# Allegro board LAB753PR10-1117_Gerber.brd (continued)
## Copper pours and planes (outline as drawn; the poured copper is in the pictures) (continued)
VCORE_VDDP on BOTTOM (solid shape): 135.66,125.98 135.66,125.9 135.02,125.26 133.36,125.26 132.53,124.43 132.53,124.17 132.91,123.79 132.91,123.6 132.65,123.34 132.4,123.34 132.02,123.73 132.02,124.11 131.64,124.49 131.64,124.88 132.77,126.02 132.96,126.02 133.24,125.75 134.39,125.75 134.65,125.48 134.95,125.48 135.51,126.04 135.59,126.04
VID_PLLVDD on TOP (solid shape): 153.84,99.44 153.84,98.99 154.94,97.88 154.94,96.87 154.78,96.72 154.02,96.72 153.8,96.49 153.8,95.54 153.61,95.36 152.6,95.36 152.42,95.54 152.42,99.4 152.54,99.53 153.74,99.53
VL on TOP (solid shape): 27.18,31.08 27.18,28.98 27.12,28.92 24.46,28.92 24.42,28.96 24.42,29.11 24.45,29.14 25.41,29.14 25.48,29.21 25.82,29.21 25.83,29.21 26.08,29.21 26.22,29.35 26.22,29.44 26.22,29.45 26.27,29.62 26.22,29.79 26.22,29.8 26.22,31.04 26.3,31.13 27.13,31.13
N3691782 on BOTTOM (solid shape): 257.97,29.04 257.97,27.05 257.81,26.88 256.15,26.88 256.07,26.96 256.07,27.97 256.74,28.64 256.74,29.2 256.78,29.23 257.78,29.23
N4123550 on TOP (solid shape): 36.64,20.92 36.64,20.28 35.56,19.2 35.56,18.76 35.37,18.57 33.78,18.57 33.72,18.63 33.72,19.65 33.78,19.71 34.42,19.71 35.69,20.98 36.58,20.98
N4124695 on TOP (solid shape): 24.83,33.86 24.83,33.23 23.1,33.23 23,33.33 23,33.81 23.08,33.89 24.81,33.89
N16788038 on TOP (solid shape): 44.83,21.05 44.83,20.22 44.58,19.97 42.93,19.97 42.8,20.09 42.8,21.11 42.93,21.24 44.64,21.24
N16788038 on BOTTOM (solid shape): 39.11,18.3 39.11,17.77 39.08,17.74 38.46,17.74 38.2,17.49 38.2,16.05 38.16,16.01 37.6,16.01 37.33,16.28 37.33,17.3 36.9,17.74 36.9,18.12 37.12,18.34 39.07,18.34
N18410136 on BOTTOM (solid shape): 137.29,107.28 137.29,106.52 137.19,106.42 135.06,106.42 134.99,106.49 134.99,107.34 135.06,107.41 137.16,107.41
N20620737 on TOP (solid shape): 182.86,30.16 182.86,29.58 182.8,29.52 181.43,29.52 181.22,29.31 181.22,28.74 181.22,28.74 181.22,28.53 181.13,28.44 181.13,27.57 181.06,27.5 180.93,27.5 180.87,27.57 180.87,28.76 180.95,28.84 180.95,29.02 180.95,29.03 180.96,29.14 180.95,29.24 180.95,29.25 180.95,29.38 180.8,29.53 180.71,29.53 180.65,29.59 180.65,30.19 180.71,30.25 182.77,30.25
N26316553 on TOP (solid shape): 104.02,119.98 104.02,117.69 103.89,117.57 103.38,117.57 103.25,117.69 103.25,118.65 102.81,119.09 102.49,119.09 102.3,119.28 102.3,119.66 102.43,119.79 102.94,119.79 103.25,120.11 103.89,120.11
N27543768 on BOTTOM (solid shape): 268,37.42 268,35.41 266.74,34.15 266.74,33.33 265.88,32.46 265.88,31.74 265.63,31.5 265.44,31.5 264.33,32.61 264.33,33.84 264.84,34.34 264.84,36.51 266.51,38.19 267.22,38.19
N27863843 on TOP (solid shape): 158.75,21.05 158.75,20.47 159.2,20.03 159.83,20.03 160.68,19.18 160.68,18.1 160.61,18.02 160.48,18.02 160.4,18.1 160.4,18.7 159.64,19.46 158.88,19.46 158.15,20.19 158.15,21.08 158.18,21.11 158.69,21.11
N30468201 on BOTTOM (solid shape): 32.16,16.83 32.63,16.83 32.77,16.69 32.77,15.65 32.58,15.46 32.2,15.46 31.18,16.47 31.18,17.22 31.35,17.38 31.61,17.38
N30468201 on BOTTOM (solid shape): 39.82,18.33 39.82,17.3 39.42,16.91 38.57,16.91 38.52,16.95 38.52,17.47 38.57,17.52 39.07,17.52 39.23,17.68 39.23,18.29 39.36,18.41 39.74,18.41
N30468201 on IN4 (solid shape): 39.82,18.32 39.82,17.36 38.25,15.8 32.18,15.8 31.18,16.8 31.18,17.02 36.27,17.02 36.27,16.97 36.28,16.92 36.3,16.86 36.32,16.82 36.35,16.77 36.39,16.73 36.43,16.7 36.47,16.67 36.52,16.65 36.58,16.64 36.63,16.64 36.68,16.64 36.73,16.65 36.78,16.67 36.83,16.7 36.87,16.73 36.91,16.77 36.94,16.82 36.96,16.86 36.98,16.92 36.98,16.97 36.98,17.02 36.98,17.07 36.96,17.13 36.94,17.17 36.91,17.22 36.87,17.26 36.83,17.29 36.78,17.32 36.73,17.34 36.68,17.35 36.63,17.35 36.58,17.35 36.52,17.34 36.47,17.32 36.43,17.29 36.39,17.26 36.35,17.22 36.32,17.17 36.3,17.13 36.28,17.07 36.27,17.02 31.18,17.02 31.18,17.33 31.51,17.66 36.81,17.66 36.93,17.53 37.89,17.53 38.8,18.44 39.69,18.44
N30503669 on BOTTOM (solid shape): 40.58,17.11 40.58,16.22 40.45,16.09 40.45,16.09 40.38,16.03 40.07,16.03 40.02,15.98 38.59,15.98 38.52,16.04 38.52,16.56 38.56,16.6 39.42,16.6 40.12,17.3 40.39,17.3
N37505012 on BOTTOM (solid shape): 21.26,9.4 21.26,8.42 20.94,8.1 19.53,8.1 19.42,8.21 19.42,9.02 19.53,9.13 19.94,9.13 20.4,9.59 21.06,9.59
N201737633 on BOTTOM (solid shape): 132.7,129.75 132.7,129.45 131.38,128.13 131.13,128.13 130.54,128.73 130.54,128.97 131.91,130.34 132.11,130.34
N201737689 on BOTTOM (solid shape): 134.64,121.21 134.64,121.09 134.17,120.62 133.97,120.62 132.47,122.13 132.47,122.34 132.9,122.77 133.09,122.77
N201738085 on TOP (solid shape): 101.98,117.31 101.98,115.72 101.92,115.66 101.09,115.66 101.03,115.72 101.03,117.38 101.09,117.44 101.86,117.44
N206179634 on TOP (solid shape): 192.76,31.89 192.76,30.98 192.65,30.88 191.79,30.88 191.5,30.58 191.5,30.13 191.42,30.05 190.64,30.05 190.57,30.12 190.57,30.86 191,31.29 191,31.77 191.16,31.93 192.71,31.93

Small or netless copper shapes (teardrops, artwork), in the pictures only: 40 on TOP, 293 on BOTTOM, 1 on IN1, 2 on IN2, 2 on IN3, 1 on IN4, 2 on IN5, 1 on IN6

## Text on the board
Ref Des/Silkscreen Bottom: H24 | DIMM 1 | DIMM 2 | DDR3L SO-DIMM | A | CPU | FAN | BL | MK | KB | GPU | DC-IN | BATT | HDD | RTC | K | P | AW 15 Only | WLAN
User.Comments: LAB753P | 2015-11-17 | 2014-11-17 | AAP20 | Minjia
Ref Des/Silkscreen Top: A | 5 | 4 | 6 | POWER | LIGHT | TRON | LOGO | 2 | EDP | 3 | IO | SPEAKER | 1
IN5: IN5
IN6: IN6
BODY_CENTER: AGND | +3VALW | +5VALW | GND | +VCC_CORE | +1.35V | +VGA_CORE | +3VS | +1.35VS_VGA | +1.05VS | GPU_B++
COMPVAL_TYPE_TOP: 320.22 | 228.05 | 212.04 | 191.34 | 160.54 | 158.39 | 142.54 | 111.64 | 107.64 | 4.82 | 2.56 | 137.06 | 116.26 | 114.06 | 97.63 | 85.76 | 67.76 | 57.89 | 39.59 | 0.00 | 2.74 | 28.76 | 140.96 | 133.36 | 128.86 | 26.01 | 5.19 | 294.24 | 7.06 | 148.53 | 9.14 | 10.46
COMPVAL_TYPE_BOTTOM: TP | 146.00 | 342.00 | 150.30
PAGE_OUTLINE: 136.16 | 79.76 | 47.18 | 31.76 | 27.76 | 18.76 | 4.46 | 2.19 | 2.01 | 270.80 | 252.89 | 221.24 | 161.59 | 151.54 | 110.54 | 89.59 | 24.56 | 277.06 | 274.89 | 263.81 | 244.54 | 220.19 | 194.29 | 169.59 | 165.21 | 158.39 | 134.89 | 108.89 | 85.39 | 68.84 | 29.36 | 0.00 | 10.46 | 42.12 | 31.26 | 29.02 | 26.53 | 24.51 | 5.96 | 3.39 | 2.74
User.7: TP | 146.00 | 342.00 | 150.30
User.9: V-CUT
User.10: 261.54 | 252.54 | 3.00 | 232.54 | 215.34 | 199.74 | 196.64 | 193.50 | 184.60 | 173.14 | 170.34 | 2.35 | 5.00 | 133.54 | 126.54 | 1.85 | 104.54 | 94.54 | 12.54 | 2.44 | 0.49 | 9.46 | 143.26 | 137.91 | 121.76 | 111.76 | 102.36 | 97.36 | 85.76 | 70.04 | 68.14 | 54.97 | 54.64 | 49.84 | 36.34 | 32.26 | 0.26 | 0.00 | 2.74 | 7.04 | 1.90 | 134.31 | 99.26 | 35.26 | 0.44 | 331.54 | 316.22 | 301.04 | 269.24 | 262.24 | 187.14 | 132.36 | 129.86 | 20.04 | 12.04 | 8.46 | 10.46
User.45: trace Width | Width/space | 3.9mil | 3.6mil | 4.7 / 3.6 | 5.5 / 4 | 3.8mil | L9/L11 | 15/7 | 15/6 | L1-TOP | L2-GND1 | L3-IN1 | L4-IN2 | L5-VCC | L6-IN3 | L7-IN4 | L8-GND2 | L9-IN5 | L10-IN6 | L11-GND3 | L12-BOT | LAYER | NAME | 45 ohm | Ref | 100 ohm | FIGURE | SIZE | 8.0 | 20.0 | 22.0 | 31.0 | 35.0 | 39.0 | 110.0 | 126.0 | 138.0 | 150.0 | 43.0 | 47.0 | 63.0 | 79.0 | 55.0x28.0 | 63.0x39.0 | 71.0x20.0 | 79.0x31.0 | 87.0x28.0 | 94.0x28.0 | 102.0x28.0 | 161.0x138.0 | 91.0x79.0 | DRILL CHART: TOP to BOTTOM | ALL UNITS ARE IN MILS | TOLERANCE | +3.0/-3.0 | +2.0/-2.0 | PLATED | NON-PLATED | QTY | 8527 | 10 | 19 | 18 | 8 | 5 | 11 | 1 | 2 | 9 | 7 | 4
